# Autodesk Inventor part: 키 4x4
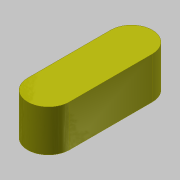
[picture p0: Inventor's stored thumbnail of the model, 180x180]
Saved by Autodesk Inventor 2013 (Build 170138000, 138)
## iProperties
Created: 2015-12
Part Number: 키 4x4
Document SubType Name: Modeling
Designer: mdu
Density: 7.86 g/cm^3
Material: 강철, 연강
Author: mdu
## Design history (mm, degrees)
sketch "스케치1"
  geometry: L1 (-2, -10)-(-2, -2) reference; L2 (2, -2)-(2, -10) reference; A1 r 2 centre (0, -2) between (2, -2) and (-2, -2) reference; A2 r 2 centre (0, -10) between (-2, -10) and (2, -10) reference; 1 further point
extrude "돌출1" new body sketch "스케치1" distance "d0" = 4; taper "d1" = 0 deg
node "솔리드1"
node "참조1"
